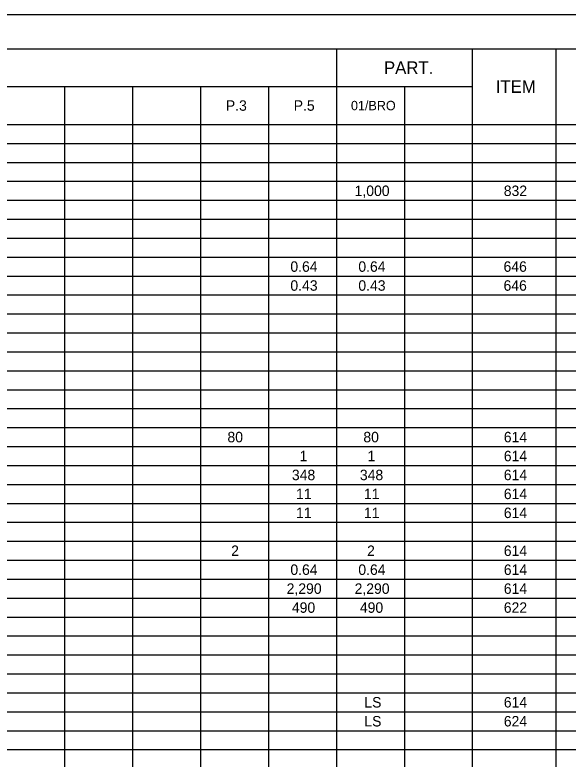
# Model space of a CAD drawing. Extents: x 0 to 34, y 0 to 22.
# Drawn here: x 8.81 to 16.99, y 11 to 22 of the extents above; entities that cross this region are included whole.
import ezdxf

# ---------------------------------------------------------------- set-up
doc = ezdxf.new("R2010")
doc.units = 0
for name, color, linetype in [('Default', 7, 'Continuous'), ('SH_Border', 7, 'Continuous'), ('SH_Cut_Line', 7, 'Continuous')]:
    doc.layers.add(name, color=color, linetype=linetype)

msp = doc.modelspace()

# ---------------------------------------------------------------- linework, layer by layer
at = {"layer": 'Default'}
for p, q in [((1.5, 21.5), (32, 21.5)), ((13.56179, 21.5), (13.56179, 0.5)), ((15.57209, 21.5), (15.57209, 0.5)), ((16.80759, 21.5), (16.80759, 0.5)), ((1.5, 20.94), (15.57209, 20.94)), ((9.54119, 20.94), (9.54119, 0.5)), ((10.54634, 20.94), (10.54634, 0.5)), ((11.55149, 20.94), (11.55149, 0.5)), ((12.55664, 20.94), (12.55664, 0.5)), ((14.56694, 20.94), (14.56694, 0.5)), ((1.5, 20.38), (32, 20.38)), ((1.5, 20.1), (32, 20.1)), ((1.5, 19.82), (32, 19.82)), ((1.5, 19.54), (32, 19.54)), ((1.5, 19.26), (32, 19.26)), ((1.5, 18.98), (32, 18.98)), ((1.5, 18.7), (32, 18.7)), ((1.5, 18.42), (32, 18.42)), ((1.5, 18.14), (32, 18.14)), ((1.5, 17.86), (32, 17.86)), ((1.5, 17.58), (32, 17.58)), ((1.5, 17.3), (32, 17.3)), ((1.5, 17.02), (32, 17.02)), ((1.5, 16.74), (32, 16.74)), ((1.5, 16.46), (32, 16.46)), ((1.5, 16.18), (32, 16.18)), ((1.5, 15.9), (32, 15.9)), ((1.5, 15.62), (32, 15.62)), ((1.5, 15.34), (32, 15.34)), ((1.5, 15.06), (32, 15.06)), ((1.5, 14.78), (32, 14.78)), ((1.5, 14.5), (32, 14.5)), ((1.5, 14.22), (32, 14.22)), ((1.5, 13.94), (32, 13.94)), ((1.5, 13.66), (32, 13.66)), ((1.5, 13.38), (32, 13.38)), ((1.5, 13.1), (32, 13.1)), ((1.5, 12.82), (32, 12.82)), ((1.5, 12.54), (32, 12.54)), ((1.5, 12.26), (32, 12.26)), ((1.5, 11.98), (32, 11.98)), ((1.5, 11.7), (32, 11.7)), ((1.5, 11.42), (32, 11.42)), ((1.5, 11.14), (32, 11.14))]:
    msp.add_line(p, q, dxfattribs=at)
at = {"layer": 'SH_Border'}
msp.add_lwpolyline([(1.5, 21.5), (33.5, 21.5), (33.5, 0.5), (1.5, 0.5)], close=True, dxfattribs=at)
at = {"layer": 'SH_Cut_Line'}
msp.add_lwpolyline([(0, 0), (34, 0), (34, 22), (0, 22)], close=True, dxfattribs=at)

# ---------------------------------------------------------------- texts
at = {"layer": 'Default'}
for s, height, p in [('PART.', 0.185472, (14.26567, 21.12726)), ('ITEM', 0.185472, (15.91946, 20.84726)), ('P.3', 0.15456, (11.92708, 20.58272)), ('P.5', 0.15456, (12.9307, 20.58272)), ('01/BRO', 0.139104, (13.77738, 20.59045)), ('1,000', 0.15456, (13.83145, 19.32272)), ('832', 0.15456, (16.03751, 19.32272)), ('0.64', 0.15456, (12.88137, 18.20272)), ('0.64', 0.15456, (13.88652, 18.20272)), ('646', 0.15456, (16.03385, 18.20272)), ('0.43', 0.15456, (12.88137, 17.92272)), ('0.43', 0.15456, (13.88652, 17.92272)), ('646', 0.15456, (16.03385, 17.92272)), ('80', 0.15456, (11.95052, 15.68272)), ('80', 0.15456, (13.96082, 15.68272)), ('614', 0.15456, (16.03788, 15.68272)), ('1', 0.15456, (13.01666, 15.40272)), ('1', 0.15456, (14.02181, 15.40272)), ('614', 0.15456, (16.03788, 15.40272)), ('348', 0.15456, (12.90433, 15.12272)), ('348', 0.15456, (13.90948, 15.12272)), ('614', 0.15456, (16.03788, 15.12272)), ('11', 0.15456, (12.96477, 14.84272)), ('11', 0.15456, (13.96992, 14.84272)), ('614', 0.15456, (16.03788, 14.84272)), ('11', 0.15456, (12.96477, 14.56272)), ('11', 0.15456, (13.96992, 14.56272)), ('614', 0.15456, (16.03788, 14.56272)), ('2', 0.15456, (12.00553, 14.00272)), ('2', 0.15456, (14.01583, 14.00272)), ('614', 0.15456, (16.03788, 14.00272)), ('0.64', 0.15456, (12.88137, 13.72272)), ('0.64', 0.15456, (13.88652, 13.72272)), ('614', 0.15456, (16.03788, 13.72272)), ('2,290', 0.15456, (12.8263, 13.44272)), ('2,290', 0.15456, (13.83145, 13.44272)), ('614', 0.15456, (16.03788, 13.44272)), ('490', 0.15456, (12.90378, 13.16272)), ('490', 0.15456, (13.90893, 13.16272)), ('622', 0.15456, (16.03751, 13.16272)), ('LS', 0.15456, (13.97529, 11.76272)), ('614', 0.15456, (16.03788, 11.76272)), ('LS', 0.15456, (13.97529, 11.48272)), ('624', 0.15456, (16.03788, 11.48272))]:
    msp.add_text(s, height=height, dxfattribs=at).set_placement(p)

doc.saveas('drawing.dxf')
